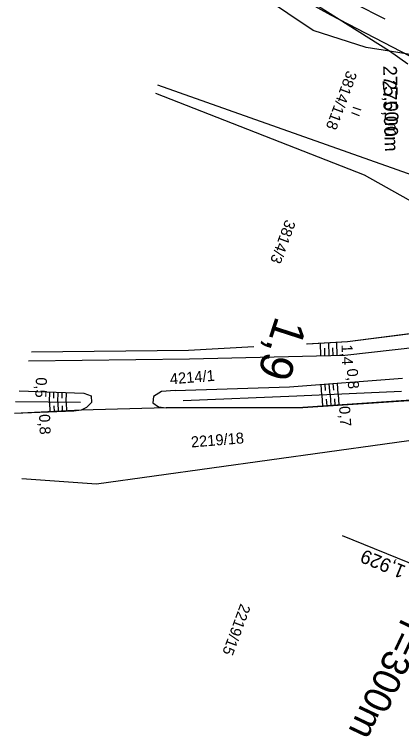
# Model space of a CAD drawing. Extents: x -659211 to -658900, y -1170600 to -1169973.
# Drawn here: x -659210.6 to -659140.2, y -1170593.1 to -1170461.6 of the extents above; entities that cross this region are included whole.
import ezdxf

# ---------------------------------------------------------------- set-up
doc = ezdxf.new("R2010")
doc.units = 0
for name, color, linetype in [('Vrstva 1', 7, 'Continuous'), ('Vrstva 48', 7, 'Continuous'), ('Vrstva 49', 7, 'Continuous'), ('Vrstva 55', 7, 'Continuous'), ('Vrstva 57', 7, 'Continuous'), ('Vrstva 58', 7, 'Continuous'), ('Vrstva 7', 7, 'Continuous')]:
    doc.layers.add(name, color=color, linetype=linetype)

msp = doc.modelspace()

# ---------------------------------------------------------------- linework, layer by layer
at = {"layer": 'Vrstva 1'}
msp.add_line((-659111.58, -1170572.64), (-659150.87, -1170556.52), dxfattribs=at)
at = {"layer": 'Vrstva 48'}
for p, q in [((-659153.47, -1170521.33), (-659153.41, -1170523.79)), ((-659151.97, -1170521.25), (-659151.91, -1170523.76)), ((-659154.97, -1170521.42), (-659154.91, -1170523.83)), ((-659154.2, -1170522.35), (-659154.16, -1170523.81)), ((-659152.7, -1170522.29), (-659152.66, -1170523.78)), ((-659154.67, -1170530.89), (-659154.81, -1170528.96)), ((-659153.97, -1170530.08), (-659154.06, -1170528.9)), ((-659153.17, -1170530.83), (-659153.32, -1170528.84)), ((-659152.48, -1170529.99), (-659152.57, -1170528.79)), ((-659151.67, -1170530.76), (-659151.82, -1170528.73)), ((-659204.2, -1170532.16), (-659204.13, -1170530.35)), ((-659203.42, -1170531.45), (-659203.39, -1170530.38)), ((-659202.7, -1170532.18), (-659202.64, -1170530.4)), ((-659201.92, -1170531.48), (-659201.89, -1170530.43)), ((-659201.2, -1170532.2), (-659201.14, -1170530.46)), ((-659154.67, -1170530.89), (-659154.53, -1170532.91)), ((-659153.86, -1170531.66), (-659153.78, -1170532.86)), ((-659153.17, -1170530.83), (-659153.04, -1170532.81)), ((-659152.36, -1170531.58), (-659152.29, -1170532.76)), ((-659151.67, -1170530.76), (-659151.54, -1170532.72)), ((-659204.2, -1170532.16), (-659204.13, -1170534)), ((-659203.42, -1170532.89), (-659203.38, -1170533.97)), ((-659202.7, -1170532.18), (-659202.63, -1170533.94)), ((-659201.92, -1170532.88), (-659201.88, -1170533.91)), ((-659201.2, -1170532.2), (-659201.13, -1170533.88))]:
    msp.add_line(p, q, dxfattribs=at)
at = {"layer": 'Vrstva 49'}
for p, q in [((-659153.04, -1170461.79), (-659168, -1170453.31)), ((-659148.72, -1170459.61), (-659143.2, -1170462.43)), ((-659131.99, -1170472.65), (-659153.04, -1170461.79)), ((-659149.99, -1170521.14), (-659124.16, -1170517.95)), ((-659157.29, -1170521.55), (-659149.99, -1170521.14)), ((-659123.1, -1170520.57), (-659150.5, -1170523.73)), ((-659178.89, -1170522.74), (-659167.04, -1170522.08)), ((-659207.5, -1170523.05), (-659178.89, -1170522.74)), ((-659150.5, -1170523.73), (-659178.73, -1170524.35)), ((-659178.73, -1170524.35), (-659208.03, -1170524.74)), ((-659160.55, -1170529.39), (-659140, -1170527.85)), ((-659209.72, -1170530.15), (-659197.93, -1170530.57)), ((-659197.93, -1170530.57), (-659196.62, -1170531.07)), ((-659183.85, -1170530.24), (-659185.29, -1170531.16)), ((-659181.34, -1170530.09), (-659183.85, -1170530.24)), ((-659181.34, -1170530.09), (-659160.55, -1170529.39)), ((-659140.19, -1170530.27), (-659159.23, -1170531.09)), ((-659196.62, -1170531.07), (-659196.55, -1170532.27)), ((-659185.29, -1170531.16), (-659185.38, -1170532.29)), ((-659159.23, -1170531.09), (-659179.9, -1170531.95)), ((-659158.12, -1170533.15), (-659136.04, -1170531.7)), ((-659210.42, -1170532.09), (-659198.58, -1170532.22)), ((-659197.47, -1170533.16), (-659198.45, -1170533.62)), ((-659196.55, -1170532.27), (-659197.47, -1170533.16)), ((-659185.38, -1170532.29), (-659184.35, -1170533.02)), ((-659184.35, -1170533.02), (-659183.01, -1170533.2)), ((-659183.01, -1170533.2), (-659158.12, -1170533.15)), ((-659199.8, -1170533.83), (-659210.58, -1170534.25)), ((-659198.45, -1170533.62), (-659199.8, -1170533.83))]:
    msp.add_line(p, q, dxfattribs=at)
at = {"layer": 'Vrstva 55'}
msp.add_line((-659096.3, -1170505.72), (-659184.52, -1170474.53), dxfattribs=at)
for points in [[(-659087.06, -1170477.24), (-659142.34, -1170468.31), (-659172.43, -1170449.35), (-659178.5, -1170444.97)], [(-659142.34, -1170468.31), (-659146.59, -1170467.66), (-659156.24, -1170464.55), (-659179.46, -1170448.88)], [(-659139, -1170470.65), (-659142.34, -1170468.31)], [(-659157.46, -1170521.55), (-659149.99, -1170521.14), (-659132.61, -1170518.88), (-659125.34, -1170502.97), (-659146.92, -1170490.88), (-659184.85, -1170476)], [(-659207.5, -1170523.05), (-659178.89, -1170522.74), (-659167.04, -1170522.07)], [(-659136.62, -1170531.73), (-659158.12, -1170533.15), (-659183.01, -1170533.2), (-659198.45, -1170533.62), (-659210.58, -1170534.25)], [(-659122.22, -1170536.93), (-659195.64, -1170547.12), (-659209.21, -1170546.14)]]:
    msp.add_lwpolyline(points, dxfattribs=at)
at = {"layer": 'Vrstva 58'}
for p, q in [((-659147.53, -1170479.08), (-659148.94, -1170478.55)), ((-659149.29, -1170479.49), (-659147.89, -1170480.02))]:
    msp.add_line(p, q, dxfattribs=at)

# ---------------------------------------------------------------- texts
at = {"layer": 'Vrstva 1'}
for s, height, rotation, p in [('275,00m', 2.5, 271.797, (-659143.51, -1170470.99)), ('275,00m', 2.5, 271.7993, (-659143.59, -1170473.62)), ('km 1,929', 2.5, 157.6933, (-659134.23, -1170564.13)), ('r=300m', 5, 244.6176, (-659140.12, -1170571.4))]:
    msp.add_text(s, height=height, rotation=rotation, dxfattribs=at).set_placement(p)
at = {"layer": 'Vrstva 48'}
for s, rotation, p in [('1,4', 271.2791, (-659151.08, -1170521.72)), ('0,8', 274.28, (-659150.13, -1170526.15)), ('0,5', 267.9771, (-659206.66, -1170527.64)), ('0,7', 273.7517, (-659151.53, -1170532.97)), ('0,8', 272.2182, (-659206.12, -1170534.41))]:
    msp.add_text(s, height=2, rotation=rotation, dxfattribs=at).set_placement(p)
at = {"layer": 'Vrstva 57'}
for s, rotation, p in [('3814/118', 249.6006, (-659150.07, -1170471.7)), ('3814/3', 249.6006, (-659161.24, -1170498.84)), ('4214/1', 4.6175, (-659182.22, -1170528.96)), ('2219/18', 4.6175, (-659178.39, -1170540.45)), ('2219/15', 249.6006, (-659169.43, -1170568.74))]:
    msp.add_text(s, height=2, rotation=rotation, dxfattribs=at).set_placement(p)
at = {"layer": 'Vrstva 7'}
msp.add_text('1,9', height=6, rotation=252.1334, dxfattribs=at).set_placement((-659163, -1170516.37))

doc.saveas('drawing.dxf')
